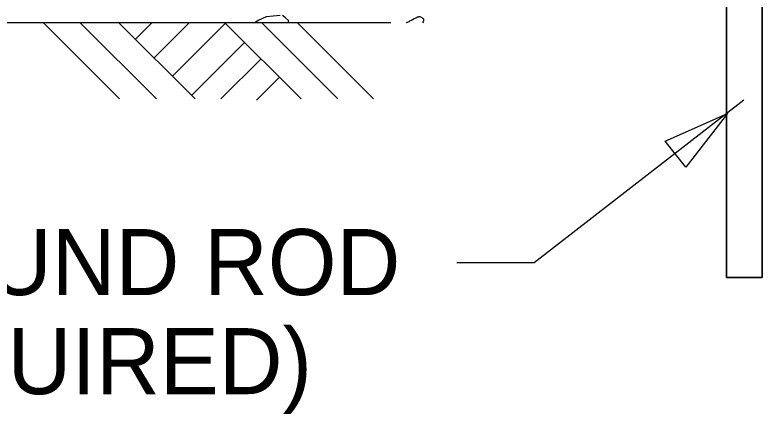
# Model space of a CAD drawing. Extents: x 1299104.8 to 1299141.6, y 239639.8 to 239661.8.
# Drawn here: x 1299112.832 to 1299114.188, y 239646.159 to 239646.884 of the extents above; entities that cross this region are included whole.
import ezdxf

# ---------------------------------------------------------------- set-up
doc = ezdxf.new("R2010")
doc.units = 0
doc.layers.add('DIM TXT', color=7, linetype='Continuous')

msp = doc.modelspace()

# ---------------------------------------------------------------- linework, layer by layer
at = {"layer": 'DIM TXT'}
for p, q in [((1299113.4414, 239646.8701), (1299112.6881, 239646.8701)), ((1299113.5145, 239646.8701), (1299112.6881, 239646.8701)), ((1299113.0218, 239646.7318), (1299112.8845, 239646.8692)), ((1299113.0887, 239646.7318), (1299112.9513, 239646.8692)), ((1299113.1592, 239646.7318), (1299113.0196, 239646.8715)), ((1299113.0812, 239646.8707), (1299113.0508, 239646.8403)), ((1299113.1488, 239646.8707), (1299113.085, 239646.8068)), ((1299113.2156, 239646.8707), (1299113.1176, 239646.7727)), ((1299113.3515, 239646.7318), (1299113.2127, 239646.8707)), ((1299113.4183, 239646.7318), (1299113.2795, 239646.8707)), ((1299113.483, 239646.7318), (1299113.3449, 239646.8699)), ((1299113.249, 239646.8343), (1299113.1532, 239646.7385)), ((1299113.2788, 239646.8046), (1299113.206, 239646.7318)), ((1299113.3121, 239646.7712), (1299113.2706, 239646.7296))]:
    msp.add_line(p, q, dxfattribs=at)
for points in [[(1299114.1235, 239649.2232), (1299114.1882, 239649.215), (1299114.1882, 239646.4078), (1299114.1235, 239646.4078)], [(1299114.0126, 239646.6553), (1299114.1256, 239646.7057), (1299114.0497, 239646.6081)]]:
    msp.add_lwpolyline(points, close=True, dxfattribs=at)
for points in [[(1299114.1235, 239646.4078), (1299114.1882, 239646.4078), (1299114.1882, 239649.215), (1299114.1235, 239649.2232), (1299114.1235, 239646.4078)], [(1299113.3136, 239646.8832), (1299113.2883, 239646.881), (1299113.2736, 239646.8746), (1299113.2675, 239646.8701)], [(1299113.3292, 239646.8701), (1299113.3288, 239646.8744), (1299113.3234, 239646.879), (1299113.3178, 239646.8836)], [(1299113.634, 239646.435), (1299113.7747, 239646.435), (1299114.1551, 239646.7304)]]:
    msp.add_lwpolyline(points, dxfattribs=at)
msp.add_open_spline([(1299113.5427, 239646.8701), (1299113.5434, 239646.8705), (1299113.5441, 239646.8708), (1299113.5505, 239646.8744), (1299113.5563, 239646.8776), (1299113.5651, 239646.8823), (1299113.5696, 239646.881), (1299113.5746, 239646.8768), (1299113.5739, 239646.873), (1299113.5721, 239646.8701)], degree=3, dxfattribs=at)

# ---------------------------------------------------------------- texts
for s, p in [('GROUND ROD', (1299112.4174, 239646.3756)), ('(REQUIRED)', (1299112.4174, 239646.1956))]:
    msp.add_text(s, height=0.12, dxfattribs=at).set_placement(p)

doc.saveas('drawing.dxf')
